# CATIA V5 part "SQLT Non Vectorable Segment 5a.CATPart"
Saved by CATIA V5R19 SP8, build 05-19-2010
Part number: SQLT Non Vectorable Segment 5a
Publications: "Droite.1", "Plan.1", "Plan.2", "Droite.2", "Droite.3"
Bounding box of the stored display mesh (mm): x -150 to 150, y 680 to 815, z 250 to 550
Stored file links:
  G:\EU_thinkMotion\CFAO_2010\MMS_groupe3\MMS_groupe3\A reprendre\fovide\fovide\SQLT Non Vectorable Segment 5a.CATPart
  G:\EU_thinkMotion\CFAO_2010\MMS_groupe3\MMS_groupe3\A reprendre\fovide\fovide\fovide.CATProduct
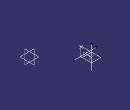
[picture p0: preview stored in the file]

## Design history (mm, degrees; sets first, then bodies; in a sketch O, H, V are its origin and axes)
Set1
  Point1 "Point.G": linked copy from another document
  Point2 "Point.H": linked copy from another document
  Plane1: linked copy from another document
  Point3 "Point.J": linked copy from another document
Set2 "set Non Vectorable Segment"
  Line1: type PtPt, FirstPoint Point1, SecondPoint Point2
  Plane2: type OffsetPt, RefPlane xy-plane, RefPoint Point1
  Plane3: type OffsetPt, RefPlane yz-plane, RefPoint Point2
  Line2: type Normal, RefPoint Point2, RefSkin Plane3, Start -150, End 150
  Line3: type Normal, RefPoint Point1, RefSkin Plane2, Start -150, End 150
Body1 (main body)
